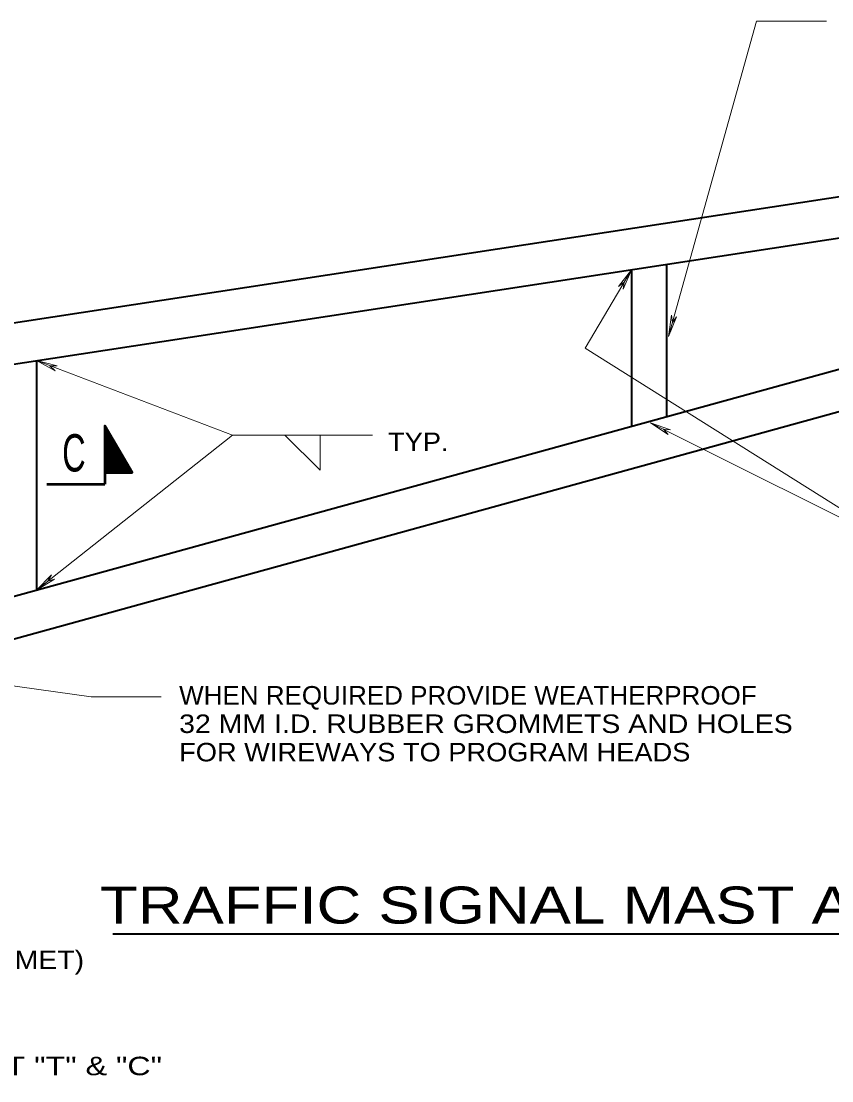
# Model space of a CAD drawing. Extents: x 312583 to 312854, y 144419 to 144597.
# Drawn here: x 312755.82 to 312789.11, y 144523.9 to 144567.41 of the extents above; entities that cross this region are included whole.
import ezdxf
from ezdxf.enums import TextEntityAlignment as Align

# ---------------------------------------------------------------- set-up
doc = ezdxf.new("R2010")
doc.units = 0
doc.header["$LTSCALE"] = 0.3
doc.layers.add('1', color=7, linetype='Continuous', lineweight=40)

msp = doc.modelspace()

# ---------------------------------------------------------------- linework, layer by layer
at = {"layer": '1', "lineweight": 13}
for p, q in [((312782.3969, 144554.4728), (312786.0155, 144567.4142)), ((312786.0155, 144567.4142), (312788.8905, 144567.4142)), ((312780.8789, 144557.2098), (312780.3499, 144556.5198)), ((312780.8789, 144557.2098), (312780.5339, 144556.4048)), ((312780.3499, 144556.5198), (312780.5799, 144556.6962)), ((312780.5339, 144556.4048), (312780.5799, 144556.6962)), ((312782.3969, 144554.4728), (312782.5272, 144555.3392)), ((312782.3969, 144554.4728), (312782.7342, 144555.2778)), ((312782.5272, 144555.3392), (312782.5579, 144555.0478)), ((312782.7342, 144555.2778), (312782.5579, 144555.0478)), ((312756.4452, 144553.4762), (312757.2195, 144553.0622)), ((312756.4452, 144553.4762), (312757.2962, 144553.2615)), ((312757.2195, 144553.0622), (312756.9972, 144553.2615)), ((312757.2962, 144553.2615), (312756.9972, 144553.2615)), ((312781.6609, 144550.9232), (312782.3892, 144550.4402)), ((312781.6609, 144550.9232), (312782.4812, 144550.6318)), ((312770.2452, 144550.4095), (312764.4952, 144550.4095)), ((312782.3892, 144550.4402), (312782.1899, 144550.6625)), ((312782.4812, 144550.6318), (312782.1899, 144550.6625)), ((312756.4452, 144544.0462), (312757.0585, 144544.6748)), ((312756.4452, 144544.0462), (312757.1889, 144544.5062)), ((312757.0585, 144544.6748), (312756.9052, 144544.4142)), ((312757.1889, 144544.5062), (312756.9052, 144544.4142)), ((312758.6915, 144539.6685), (312761.5665, 144539.6685))]:
    msp.add_line(p, q, dxfattribs=at)
at = {"layer": '1'}
for p, q in [((312729.8495, 144551.1072), (312833.1655, 144566.9005)), ((312729.8495, 144549.4052), (312833.4185, 144565.2368)), ((312729.8495, 144536.7322), (312829.0255, 144564.0332)), ((312729.8649, 144534.9918), (312829.4702, 144562.4155)), ((312782.3202, 144557.4245), (312782.3202, 144551.1762)), ((312780.8789, 144557.2098), (312780.8789, 144550.7775)), ((312756.4452, 144553.4762), (312756.4452, 144544.0462)), ((312759.5774, 144529.9318), (312827.1878, 144529.9318))]:
    msp.add_line(p, q, dxfattribs=at)
at = {"layer": '1', "lineweight": 35}
for p, q in [((312759.2589, 144550.7775), (312759.2742, 144550.7775)), ((312759.2589, 144550.7468), (312759.2819, 144550.7545)), ((312759.2589, 144550.7162), (312759.2972, 144550.7392)), ((312759.2589, 144550.6932), (312759.3049, 144550.7162)), ((312759.2589, 144550.6625), (312759.3202, 144550.6932)), ((312759.2589, 144550.6395), (312759.3279, 144550.6778)), ((312759.2589, 144550.6088), (312759.3432, 144550.6548)), ((312759.2589, 144550.5782), (312759.3509, 144550.6318)), ((312759.2589, 144550.5475), (312759.3662, 144550.6165)), ((312759.2589, 144550.5245), (312759.3739, 144550.5935)), ((312759.2589, 144550.5015), (312759.3892, 144550.5705)), ((312759.2589, 144550.4708), (312759.3969, 144550.5475)), ((312759.2589, 144550.4478), (312759.4122, 144550.5322)), ((312759.2589, 144550.4172), (312759.4275, 144550.5092)), ((312759.2589, 144550.3865), (312759.4352, 144550.4862)), ((312759.2589, 144550.3558), (312759.4505, 144550.4708)), ((312759.2589, 144550.3328), (312759.4659, 144550.4478)), ((312759.2589, 144550.3022), (312759.4735, 144550.4248)), ((312759.2589, 144550.2792), (312759.4889, 144550.4095)), ((312759.2589, 144550.2485), (312759.4965, 144550.3865)), ((312759.2589, 144550.2178), (312759.5119, 144550.3635)), ((312759.2589, 144550.1948), (312759.5195, 144550.3482)), ((312759.2589, 144550.1642), (312759.5349, 144550.3175)), ((312759.2589, 144550.1412), (312759.5425, 144550.3022)), ((312759.2589, 144550.1105), (312759.5579, 144550.2792)), ((312759.2589, 144550.0798), (312759.5655, 144550.2562)), ((312759.2589, 144550.0568), (312759.5809, 144550.2408)), ((312759.2589, 144550.0262), (312759.5885, 144550.2178)), ((312759.2589, 144550.0032), (312759.6039, 144550.1948)), ((312759.2589, 144549.9725), (312759.6192, 144550.1795)), ((312759.2589, 144549.9495), (312759.6269, 144550.1565)), ((312759.2589, 144549.9188), (312759.6422, 144550.1335)), ((312759.2589, 144549.8882), (312759.6575, 144550.1182)), ((312759.2589, 144549.8575), (312759.6652, 144550.0952)), ((312759.2589, 144549.8345), (312759.6805, 144550.0722)), ((312759.2589, 144549.8115), (312759.6882, 144550.0492)), ((312759.2589, 144549.7808), (312759.7035, 144550.0338)), ((312759.2589, 144549.7502), (312759.7112, 144550.0108)), ((312759.2589, 144549.7272), (312759.7265, 144549.9878)), ((312759.2589, 144549.6965), (312759.7342, 144549.9725)), ((312759.2589, 144549.6658), (312759.7495, 144549.9495)), ((312759.2589, 144549.6428), (312759.7572, 144549.9265)), ((312759.2589, 144549.6122), (312759.7725, 144549.9112)), ((312759.2589, 144549.5815), (312759.7802, 144549.8882)), ((312759.2589, 144549.5585), (312759.7955, 144549.8652)), ((312759.2589, 144549.5048), (312759.8185, 144549.8192)), ((312759.2589, 144549.4742), (312759.8339, 144549.8038)), ((312759.2589, 144549.4512), (312759.8415, 144549.7808)), ((312759.2589, 144549.4205), (312759.8569, 144549.7578)), ((312759.2589, 144549.3898), (312759.8645, 144549.7425)), ((312759.2589, 144549.3592), (312759.8799, 144549.7195)), ((312759.2589, 144549.3362), (312759.8875, 144549.6965)), ((312759.2589, 144549.3132), (312759.9029, 144549.6812)), ((312759.2589, 144549.2518), (312759.9259, 144549.6352)), ((312759.2589, 144549.2288), (312759.9335, 144549.6198)), ((312759.2589, 144549.1982), (312759.9489, 144549.5968)), ((312759.2589, 144549.1675), (312759.9642, 144549.5738)), ((312759.2589, 144549.1445), (312759.9719, 144549.5508)), ((312759.2589, 144549.1138), (312759.9872, 144549.5355)), ((312759.2665, 144549.5278), (312759.8109, 144549.8498)), ((312759.2665, 144549.2825), (312759.9105, 144549.6582)), ((312759.2589, 144549.0832), (312760.0025, 144549.5125)), ((312759.2589, 144549.0065), (312760.0332, 144549.4512)), ((312759.2589, 144548.9758), (312760.0485, 144549.4282)), ((312759.2589, 144548.9528), (312760.0562, 144549.4128)), ((312759.2589, 144548.9222), (312760.0715, 144549.3898)), ((312759.2589, 144548.8915), (312760.0792, 144549.3668)), ((312759.2665, 144549.0602), (312760.0102, 144549.4895)), ((312759.2665, 144549.0295), (312760.0255, 144549.4742)), ((312759.2819, 144548.8762), (312760.0945, 144549.3515)), ((312759.3355, 144548.8762), (312760.1022, 144549.3208)), ((312759.3739, 144548.8762), (312760.1175, 144549.3055)), ((312759.4275, 144548.8762), (312760.1252, 144549.2825)), ((312759.4735, 144548.8762), (312760.1405, 144549.2595)), ((312759.5195, 144548.8762), (312760.1559, 144549.2442)), ((312759.5655, 144548.8762), (312760.1635, 144549.2212)), ((312759.6192, 144548.8762), (312760.1789, 144549.1982)), ((312759.6652, 144548.8762), (312760.1942, 144549.1828)), ((312759.7112, 144548.8762), (312760.2019, 144549.1598)), ((312759.7649, 144548.8762), (312760.2172, 144549.1445)), ((312759.8109, 144548.8762), (312760.2249, 144549.1215)), ((312759.8569, 144548.8762), (312760.2402, 144549.0985)), ((312759.9105, 144548.8762), (312760.2479, 144549.0832)), ((312759.9565, 144548.8762), (312760.2632, 144549.0525)), ((312760.0025, 144548.8762), (312760.2709, 144549.0372)), ((312760.0485, 144548.8762), (312760.2862, 144549.0142)), ((312760.1022, 144548.8762), (312760.2939, 144548.9912)), ((312760.1405, 144548.8762), (312760.3092, 144548.9758)), ((312760.1942, 144548.8762), (312760.3169, 144548.9528)), ((312760.2402, 144548.8762), (312760.3322, 144548.9298)), ((312760.2939, 144548.8762), (312760.3475, 144548.9145)), ((312760.3399, 144548.8762), (312760.3552, 144548.8915))]:
    msp.add_line(p, q, dxfattribs=at)
at = {"layer": '1', "lineweight": 53}
for p in [(312759.2589, 144548.8762), (312756.8669, 144548.4008)]:
    msp.add_line(p, (312759.2589, 144548.4008), dxfattribs=at)
at = {"layer": '1', "lineweight": 13}
for points in [[(312780.8789, 144557.2098), (312778.9775, 144553.9822), (312792.3789, 144545.5642), (312781.6609, 144550.9232)], [(312756.4452, 144544.0462), (312764.4952, 144550.4095), (312756.4452, 144553.4762)], [(312766.6495, 144550.4095), (312768.0909, 144548.9758), (312768.0909, 144550.4095)], [(312758.6915, 144539.6685), (312732.4102, 144543.3562), (312729.8419, 144545.7635)]]:
    msp.add_lwpolyline(points, dxfattribs=at)
at = {"layer": '1', "lineweight": 53}
msp.add_lwpolyline([(312759.2589, 144548.8762), (312760.3705, 144548.8762), (312759.2589, 144550.7928)], close=True, dxfattribs=at)

# ---------------------------------------------------------------- texts
at = {"layer": '1'}
for s, height, width, p in [('C', 1.533, 0.65, (312757.9824, 144548.9222)), ('TRAFFIC SIGNAL MAST ARM FOR TYPE "T" & "C" POLES', 1.52, 1.25, (312793.1876, 144530.3583))]:
    msp.add_text(s, height=height, dxfattribs=dict(at, width=width)).set_placement(p, align=Align.CENTER)
for s, width, p in [('TYP.', 1.1, (312770.8833, 144549.7606)), ('WHEN REQUIRED PROVIDE WEATHERPROOF', 1.05, (312762.3043, 144539.3512)), ('32 MM I.D. RUBBER GROMMETS AND HOLES', 1.15, (312762.3043, 144538.1849)), ('FOR WIREWAYS TO PROGRAM HEADS', 1.1, (312762.3043, 144537.0186)), ('(32 MM I.D. RUBBER GROMMET)', 1.15, (312740.285, 144528.4885)), ('(SEE NOTE "C") TO FIT 152 MM O.D. SHAFT "T" & "C"', 1.3, (312728.6923, 144524.1301))]:
    msp.add_text(s, height=0.76, dxfattribs=dict(at, width=width)).set_placement(p)

doc.saveas('drawing.dxf')
